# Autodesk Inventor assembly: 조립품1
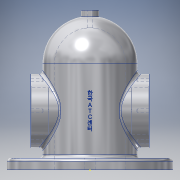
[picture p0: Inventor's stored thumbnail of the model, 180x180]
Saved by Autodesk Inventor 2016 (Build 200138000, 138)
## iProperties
Created: 2019-11
Part Number: 조립품1
Material: 일반
Document SubType Name: Assembly
Designer: 605-04
Author: 605-04
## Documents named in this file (2)
- C:\Users\605-04\Desktop\491104V1001\조립품1.iam
- C:\Users\605-04\Desktop\491104V1001\본체.ipt
